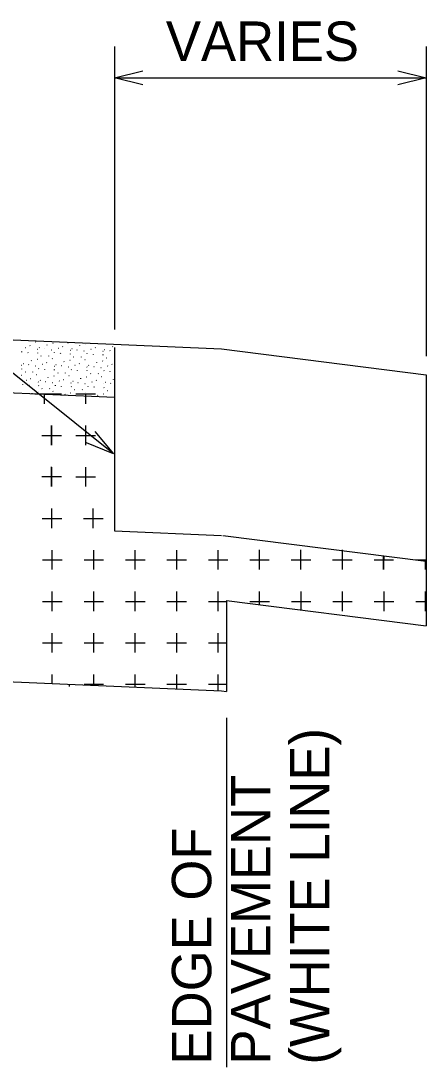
# Model space of a CAD drawing. Extents: x 0 to 34, y -1.4 to 22.
# Drawn here: x 20.126 to 21.567, y 12.439 to 16.156 of the extents above; entities that cross this region are included whole.
import ezdxf

# ---------------------------------------------------------------- set-up
doc = ezdxf.new("R2010")
doc.units = 0
doc.layers.add('SH_Text', color=7, linetype='Continuous')

msp = doc.modelspace()

# ---------------------------------------------------------------- linework, layer by layer
at = {"layer": 'SH_Text'}
for p, q in [((20.459, 16.0657), (20.459, 15.0602)), ((21.5667, 16.0657), (21.5667, 14.9647)), ((20.459, 15.9542), (21.5667, 15.9542)), ((20.4554, 14.6178), (19.5597, 15.3346)), ((20.1424, 14.9963), (20.1434, 14.9961)), ((20.1575, 15.0023), (20.1585, 15.0013)), ((20.177, 15.016), (20.178, 15.0158)), ((20.1845, 14.9896), (20.1857, 14.9895)), ((20.1909, 14.9955), (20.1919, 14.9951)), ((20.2094, 14.9913), (20.2104, 14.991)), ((20.22, 15.0045), (20.2194, 15.0058)), ((20.234, 14.9875), (20.235, 14.9873)), ((20.24, 15.0108), (20.2412, 15.0106)), ((20.2585, 14.9931), (20.2597, 14.993)), ((20.2737, 14.999), (20.2749, 14.998)), ((20.2932, 15.0128), (20.2944, 15.0126)), ((20.3009, 14.9863), (20.3019, 14.9861)), ((20.307, 14.9921), (20.3082, 14.992)), ((20.3255, 14.988), (20.3267, 14.9878)), ((20.3362, 15.0011), (20.3357, 15.0025)), ((20.3504, 14.9843), (20.3514, 14.984)), ((20.3564, 15.0076), (20.3574, 15.0075)), ((20.3749, 14.9898), (20.3759, 14.9896)), ((20.39, 14.9956), (20.3912, 14.9948)), ((20.417, 14.9831), (20.4182, 14.983)), ((20.4234, 14.989), (20.4245, 14.9886)), ((20.4419, 14.9848), (20.4429, 14.9845)), ((20.4524, 14.9978), (20.4519, 14.9991)), ((20.459, 14.9954), (20.459, 14.3443)), ((20.1295, 14.9796), (20.129, 14.981)), ((20.1515, 14.977), (20.151, 14.9783)), ((20.1634, 14.948), (20.1629, 14.9493)), ((20.1835, 14.9543), (20.1845, 14.9541)), ((20.1862, 14.9755), (20.1857, 14.977)), ((20.1972, 14.9658), (20.1982, 14.9656)), ((20.2254, 14.9645), (20.2249, 14.966)), ((20.2367, 14.9563), (20.2379, 14.956)), ((20.2459, 14.9763), (20.2454, 14.9778)), ((20.2679, 14.9736), (20.2674, 14.9751)), ((20.2797, 14.9446), (20.2792, 14.946)), ((20.2999, 14.9511), (20.3009, 14.951)), ((20.3024, 14.9723), (20.3019, 14.9736)), ((20.3135, 14.9625), (20.3145, 14.9623)), ((20.3415, 14.9613), (20.341, 14.9626)), ((20.353, 14.953), (20.354, 14.9528)), ((20.3622, 14.9731), (20.3617, 14.9745)), ((20.3842, 14.9705), (20.3837, 14.9718)), ((20.416, 14.9478), (20.417, 14.9476)), ((20.4187, 14.969), (20.4182, 14.9705)), ((20.4297, 14.9593), (20.4309, 14.959)), ((20.128, 14.9331), (20.1292, 14.933)), ((20.1297, 14.919), (20.1292, 14.9203)), ((20.1344, 14.939), (20.1355, 14.9388)), ((20.1407, 14.9093), (20.1419, 14.9091)), ((20.1529, 14.9348), (20.1539, 14.9346)), ((20.1689, 14.9081), (20.1684, 14.9095)), ((20.1775, 14.931), (20.1787, 14.9308)), ((20.1894, 14.9198), (20.1889, 14.9211)), ((20.202, 14.9366), (20.203, 14.9365)), ((20.2114, 14.9171), (20.2109, 14.9186)), ((20.2174, 14.9425), (20.2184, 14.9416)), ((20.2444, 14.93), (20.2454, 14.9296)), ((20.246, 14.9158), (20.2455, 14.9171)), ((20.2507, 14.9356), (20.2517, 14.9355)), ((20.269, 14.9315), (20.27, 14.9313)), ((20.2939, 14.9276), (20.2949, 14.9275)), ((20.3055, 14.9166), (20.305, 14.918)), ((20.3184, 14.9335), (20.3194, 14.9331)), ((20.3277, 14.914), (20.327, 14.9153)), ((20.3335, 14.9391), (20.3345, 14.9383)), ((20.3607, 14.9266), (20.3617, 14.9263)), ((20.3622, 14.9125), (20.3617, 14.9138)), ((20.3669, 14.9325), (20.368, 14.9323)), ((20.3854, 14.9281), (20.3864, 14.928)), ((20.396, 14.9413), (20.3955, 14.9428)), ((20.41, 14.9245), (20.411, 14.9243)), ((20.4219, 14.9133), (20.4214, 14.9146)), ((20.4345, 14.9301), (20.4357, 14.93)), ((20.4439, 14.9106), (20.4434, 14.9121)), ((20.4499, 14.936), (20.4509, 14.9351)), ((20.127, 14.898), (20.128, 14.8976)), ((20.1455, 14.8801), (20.1467, 14.88)), ((20.1607, 14.886), (20.1619, 14.8851)), ((20.1802, 14.8998), (20.1814, 14.8996)), ((20.1879, 14.8735), (20.1889, 14.8731)), ((20.1942, 14.8791), (20.1952, 14.879)), ((20.2125, 14.875), (20.2137, 14.8748)), ((20.2232, 14.8881), (20.2227, 14.8895)), ((20.2372, 14.8713), (20.2384, 14.871)), ((20.2434, 14.8946), (20.2444, 14.8945)), ((20.257, 14.906), (20.258, 14.9058)), ((20.2619, 14.8768), (20.2629, 14.8766)), ((20.277, 14.8826), (20.2782, 14.8818)), ((20.2852, 14.9048), (20.2847, 14.9061)), ((20.2965, 14.8965), (20.2975, 14.8963)), ((20.3104, 14.876), (20.3115, 14.8756)), ((20.3289, 14.8718), (20.3299, 14.8715)), ((20.3395, 14.8848), (20.3389, 14.8863)), ((20.3595, 14.8913), (20.3607, 14.8911)), ((20.3732, 14.9028), (20.3744, 14.9026)), ((20.378, 14.8736), (20.379, 14.8735)), ((20.3934, 14.8795), (20.3944, 14.8786)), ((20.4014, 14.9016), (20.4009, 14.903)), ((20.4127, 14.8931), (20.4139, 14.893)), ((20.4267, 14.8726), (20.4277, 14.8725)), ((20.4557, 14.8816), (20.4552, 14.883)), ((21.5668, 14.8984), (21.5668, 14.2356)), ((20.1329, 14.8633), (20.1324, 14.8648)), ((20.1549, 14.8608), (20.1544, 14.8621)), ((20.1869, 14.8381), (20.1879, 14.838)), ((20.1894, 14.8593), (20.1889, 14.8606)), ((20.2005, 14.8495), (20.2015, 14.8493)), ((20.2287, 14.8483), (20.228, 14.8496)), ((20.24, 14.84), (20.2412, 14.8398)), ((20.2492, 14.8601), (20.2487, 14.8615)), ((20.271, 14.8575), (20.2705, 14.8588)), ((20.303, 14.8348), (20.304, 14.8346)), ((20.304, 14.8701), (20.3052, 14.87)), ((20.3057, 14.856), (20.3052, 14.8575)), ((20.3169, 14.8463), (20.3179, 14.846)), ((20.3449, 14.845), (20.3444, 14.8465)), ((20.3535, 14.868), (20.3547, 14.8678)), ((20.3564, 14.8368), (20.3574, 14.8365)), ((20.3654, 14.8568), (20.3649, 14.8583)), ((20.3874, 14.8541), (20.3869, 14.8555)), ((20.4204, 14.8668), (20.4215, 14.8666)), ((20.422, 14.8526), (20.4215, 14.8541)), ((20.433, 14.843), (20.434, 14.8428)), ((20.445, 14.8685), (20.4462, 14.8683)), ((20.1665, 14.832), (20.1662, 14.833)), ((20.1751, 14.8309), (20.21, 14.8309)), ((20.2011, 14.8309), (20.2706, 14.8309)), ((20.21, 14.7961), (20.21, 14.8309)), ((20.21, 14.8309), (20.2446, 14.8309)), ((20.283, 14.8285), (20.2825, 14.8298)), ((20.3218, 14.8309), (20.3566, 14.8309)), ((20.3566, 14.7961), (20.3566, 14.8309)), ((20.3566, 14.8309), (20.3913, 14.8309)), ((20.3992, 14.8251), (20.3987, 14.8265)), ((20.4192, 14.8316), (20.4204, 14.8315)), ((20.453, 14.8196), (20.4532, 14.8195)), ((20.2353, 14.6486), (20.2353, 14.7181)), ((20.2359, 14.6834), (20.2359, 14.7181)), ((20.3566, 14.6486), (20.3566, 14.7181)), ((20.2005, 14.6834), (20.27, 14.6834)), ((20.2359, 14.6486), (20.2359, 14.6834)), ((20.2359, 14.6834), (20.2706, 14.6834)), ((20.3218, 14.6834), (20.3913, 14.6834)), ((20.2005, 14.5368), (20.27, 14.5368)), ((20.2353, 14.5019), (20.2353, 14.5714)), ((20.2359, 14.5012), (20.2359, 14.5707)), ((20.3566, 14.5359), (20.3566, 14.5707)), ((20.3218, 14.5359), (20.3566, 14.5359)), ((20.3566, 14.5012), (20.3566, 14.5359)), ((20.3566, 14.5359), (20.3913, 14.5359)), ((20.2011, 14.3886), (20.2359, 14.3886)), ((20.202, 14.3886), (20.2715, 14.3886)), ((20.2359, 14.3886), (20.2359, 14.4232)), ((20.2359, 14.3537), (20.2359, 14.3886)), ((20.2359, 14.3886), (20.2706, 14.3886)), ((20.2366, 14.3537), (20.2366, 14.4232)), ((20.3486, 14.3886), (20.4181, 14.3886)), ((20.3833, 14.3537), (20.3833, 14.4232)), ((20.2378, 14.3537), (20.2378, 14.3539)), ((20.2032, 14.2411), (20.2378, 14.2411)), ((20.2378, 14.2411), (20.2378, 14.2759)), ((20.2378, 14.2064), (20.2378, 14.2411)), ((20.2378, 14.2411), (20.2725, 14.2411)), ((20.3505, 14.2411), (20.42, 14.2411)), ((20.3853, 14.2064), (20.3853, 14.2759)), ((20.498, 14.2411), (20.5327, 14.2411)), ((20.5327, 14.2411), (20.5327, 14.2759)), ((20.5327, 14.2064), (20.5327, 14.2411)), ((20.5327, 14.2411), (20.5675, 14.2411)), ((20.6453, 14.2411), (20.7148, 14.2411)), ((20.6802, 14.2064), (20.6802, 14.2759)), ((20.7928, 14.2411), (20.8275, 14.2411)), ((20.8275, 14.2411), (20.8275, 14.2759)), ((20.8275, 14.2064), (20.8275, 14.2411)), ((20.8275, 14.2411), (20.8623, 14.2411)), ((20.9397, 14.2416), (21.0092, 14.2416)), ((20.9743, 14.2067), (20.9743, 14.2762)), ((21.087, 14.2416), (21.1218, 14.2416)), ((21.1218, 14.2416), (21.1218, 14.2762)), ((21.1218, 14.2067), (21.1218, 14.2416)), ((21.1218, 14.2416), (21.1565, 14.2416)), ((21.2343, 14.2416), (21.3038, 14.2416)), ((21.2692, 14.2067), (21.2692, 14.2762)), ((21.3818, 14.2416), (21.4165, 14.2416)), ((21.4153, 14.2064), (21.4153, 14.2547)), ((21.4165, 14.2067), (21.4165, 14.2416)), ((21.4165, 14.2416), (21.4513, 14.2416)), ((21.4172, 14.2411), (21.4172, 14.2546)), ((21.5298, 14.2416), (21.5645, 14.2416)), ((21.5645, 14.2064), (21.5645, 14.2359)), ((21.5668, 14.2356), (21.5668, 14.0067)), ((20.2378, 14.0591), (20.2378, 14.1286)), ((20.3853, 14.0937), (20.3853, 14.1286)), ((20.5327, 14.0591), (20.5327, 14.1286)), ((20.6802, 14.0937), (20.6802, 14.1286)), ((20.8275, 14.0591), (20.8275, 14.1286)), ((20.975, 14.0937), (20.975, 14.1286)), ((21.1223, 14.0629), (21.1223, 14.1286)), ((21.2697, 14.0937), (21.2697, 14.1286)), ((21.4172, 14.0591), (21.4172, 14.1286)), ((21.5645, 14.0937), (21.5645, 14.1286)), ((20.2032, 14.0937), (20.2725, 14.0937)), ((20.3505, 14.0937), (20.3853, 14.0937)), ((20.3853, 14.0591), (20.3853, 14.0937)), ((20.3853, 14.0937), (20.42, 14.0937)), ((20.498, 14.0937), (20.5675, 14.0937)), ((20.6453, 14.0937), (20.6802, 14.0937)), ((20.6802, 14.0591), (20.6802, 14.0937)), ((20.6802, 14.0937), (20.7148, 14.0937)), ((20.7928, 14.0937), (20.8573, 14.0937)), ((20.8573, 14.0966), (20.8573, 13.7737)), ((20.9402, 14.0937), (20.975, 14.0937)), ((20.975, 14.0817), (20.975, 14.0937)), ((20.975, 14.0937), (21.0097, 14.0937)), ((21.0877, 14.0937), (21.1572, 14.0937)), ((21.235, 14.0937), (21.2697, 14.0937)), ((21.2697, 14.0591), (21.2697, 14.0937)), ((21.2697, 14.0937), (21.3045, 14.0937)), ((21.3823, 14.0937), (21.4518, 14.0937)), ((21.5298, 14.0937), (21.5645, 14.0937)), ((21.5645, 14.0591), (21.5645, 14.0937)), ((21.5645, 14.0937), (21.5668, 14.0937)), ((20.2378, 13.9464), (20.2378, 13.9811)), ((20.3853, 13.9116), (20.3853, 13.9811)), ((20.5327, 13.9464), (20.5327, 13.9811)), ((20.6802, 13.9116), (20.6802, 13.9811)), ((20.8275, 13.9464), (20.8275, 13.9811)), ((20.2032, 13.9464), (20.2378, 13.9464)), ((20.2378, 13.9116), (20.2378, 13.9464)), ((20.2378, 13.9464), (20.2725, 13.9464)), ((20.3505, 13.9464), (20.42, 13.9464)), ((20.498, 13.9464), (20.5327, 13.9464)), ((20.5327, 13.9116), (20.5327, 13.9464)), ((20.5327, 13.9464), (20.5675, 13.9464)), ((20.6453, 13.9464), (20.7148, 13.9464)), ((20.7928, 13.9464), (20.8275, 13.9464)), ((20.8275, 13.9116), (20.8275, 13.9464)), ((20.8275, 13.9464), (20.8573, 13.9464)), ((20.2378, 13.8021), (20.2378, 13.8337)), ((20.3853, 13.7989), (20.3853, 13.8337)), ((20.5327, 13.7894), (20.5327, 13.8337)), ((20.6802, 13.7989), (20.6802, 13.8337)), ((20.8275, 13.7766), (20.8275, 13.8337)), ((20.2991, 13.7907), (20.2991, 13.7967)), ((20.3505, 13.7989), (20.3853, 13.7989)), ((20.3853, 13.7957), (20.3853, 13.7989)), ((20.3853, 13.7989), (20.42, 13.7989)), ((20.498, 13.7989), (20.5675, 13.7989)), ((20.6453, 13.7989), (20.6802, 13.7989)), ((20.6802, 13.7829), (20.6802, 13.7989)), ((20.6802, 13.7989), (20.7148, 13.7989)), ((20.7928, 13.7989), (20.8573, 13.7989)), ((20.8573, 13.6802), (20.8573, 12.4386))]:
    msp.add_line(p, q, dxfattribs=at)
for points in [[(20.5594, 15.9292), (20.459, 15.9542), (20.5594, 15.9794)], [(21.4665, 15.9794), (21.5667, 15.9542), (21.4665, 15.9292)], [(19.4382, 15.0512), (20.8388, 14.9906), (21.5668, 14.8984)], [(18.4848, 14.9047), (20.459, 14.8192)], [(20.3894, 14.6973), (20.4554, 14.6178), (20.3598, 14.6567)], [(20.459, 14.3443), (20.8388, 14.3279)], [(20.8437, 14.3277), (21.5668, 14.2361)], [(20.8573, 14.0966), (21.5668, 14.0067)], [(18.4848, 13.8781), (20.8388, 13.7761), (20.8573, 13.7737)]]:
    msp.add_lwpolyline(points, dxfattribs=at)

# ---------------------------------------------------------------- texts
msp.add_text('VARIES', height=0.14, dxfattribs=at).set_placement((20.6416, 16.0143))
for s, p in [('(WHITE LINE)', (21.223, 12.4476)), ('PAVEMENT', (21.013, 12.4476)), ('EDGE OF', (20.803, 12.4476))]:
    msp.add_text(s, height=0.14, rotation=90, dxfattribs=at).set_placement(p)

doc.saveas('drawing.dxf')
